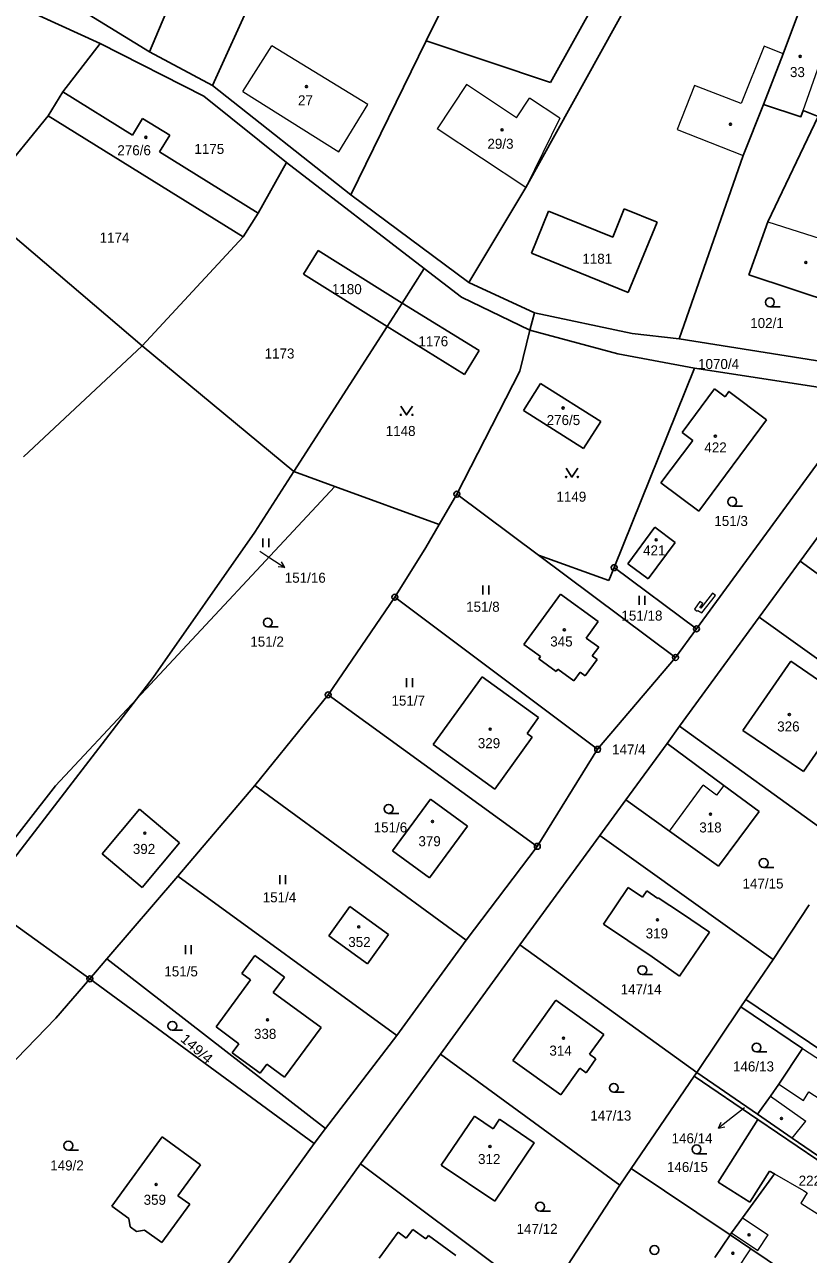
# Model space of a CAD drawing. Extents: x -694609 to -690140, y -1033292 to -1029794.
# Drawn here: x -692957.6 to -692824.6, y -1031527.4 to -1031318.8 of the extents above; entities that cross this region are included whole.
import ezdxf
from ezdxf.enums import TextEntityAlignment as Align

# ---------------------------------------------------------------- set-up
doc = ezdxf.new("R2010")
doc.units = 0
doc.header["$LTSCALE"] = 0.68
for name, color, linetype, lineweight in [('1', 7, 'Continuous', 25), ('13', 7, 'Continuous', 13), ('3', 7, 'Continuous', 25), ('4', 7, 'Continuous', 13), ('5', 7, 'Continuous', 25), ('7', 7, 'Continuous', 13), ('8', 7, 'Continuous', 25)]:
    doc.layers.add(name, color=color, linetype=linetype, lineweight=lineweight)
doc.layers.add('2', color=7, linetype='Continuous')

msp = doc.modelspace()

# ---------------------------------------------------------------- linework, layer by layer
at = {"layer": '1'}
for p, q in [((-692868.43, -1031328.64), (-692843.96, -1031284.77)), ((-692908.54, -1031291.14), (-692925.77, -1031329.14)), ((-692944.79, -1031321.99), (-692982.62, -1031304.77)), ((-692889.51, -1031321.56), (-692884.99, -1031312.35)), ((-692951.8, -1031313.97), (-692936.46, -1031323.39)), ((-692932.61, -1031314.23), (-692936.46, -1031323.39)), ((-692872.57, -1031346.43), (-692854.25, -1031313.29)), ((-692825.19, -1031313.81), (-692828.91, -1031323.74)), ((-692944.79, -1031321.99), (-692951.15, -1031330.19)), ((-692927.23, -1031330.94), (-692944.79, -1031321.99)), ((-692902.3, -1031347.66), (-692889.51, -1031321.56)), ((-692889.51, -1031321.56), (-692868.43, -1031328.64)), ((-692936.46, -1031323.39), (-692925.77, -1031329.14)), ((-692832.29, -1031332.37), (-692828.91, -1031323.74)), ((-692902.3, -1031347.66), (-692925.77, -1031329.14)), ((-692951.15, -1031330.19), (-692953.66, -1031334.24)), ((-692951.15, -1031330.19), (-692939.35, -1031337.52)), ((-692913.22, -1031342.18), (-692927.23, -1031330.94)), ((-692835.69, -1031340.98), (-692832.29, -1031332.37)), ((-692965.91, -1031349.24), (-692953.66, -1031334.24)), ((-692920.53, -1031354.81), (-692953.66, -1031334.24)), ((-692939.35, -1031337.52), (-692937.61, -1031334.72)), ((-692937.61, -1031334.72), (-692933.02, -1031337.57)), ((-692831.53, -1031352.24), (-692822.98, -1031334.36)), ((-692825.53, -1031333.39), (-692822.98, -1031334.36)), ((-692933.02, -1031337.57), (-692934.76, -1031340.37)), ((-692846.59, -1031372.09), (-692835.69, -1031340.98)), ((-692889.84, -1031360.18), (-692913.22, -1031342.18)), ((-692882.25, -1031362.52), (-692902.3, -1031347.66)), ((-692882.25, -1031362.52), (-692872.57, -1031346.43)), ((-692937.71, -1031373.28), (-692965.91, -1031349.24)), ((-692918.02, -1031350.77), (-692920.53, -1031354.81)), ((-692868.72, -1031350.42), (-692871.63, -1031357.56)), ((-692855.89, -1031350.04), (-692850.33, -1031352.3)), ((-692850.33, -1031352.3), (-692855.2, -1031364.25)), ((-692831.53, -1031352.24), (-692834.78, -1031361.26)), ((-692937.71, -1031373.28), (-692920.53, -1031354.81)), ((-692907.81, -1031357.12), (-692910.34, -1031361.15)), ((-692893.56, -1031366.02), (-692907.81, -1031357.12)), ((-692855.2, -1031364.25), (-692871.63, -1031357.56)), ((-692889.84, -1031360.18), (-692893.56, -1031366.02)), ((-692883.53, -1031365.05), (-692889.84, -1031360.18)), ((-692896.14, -1031369.98), (-692910.34, -1031361.15)), ((-692871.14, -1031367.68), (-692882.25, -1031362.52)), ((-692834.78, -1031361.26), (-692818.41, -1031366.65)), ((-692896.14, -1031369.98), (-692893.56, -1031366.02)), ((-692880.52, -1031374.09), (-692893.56, -1031366.02)), ((-692871.89, -1031370.64), (-692883.53, -1031365.05)), ((-692871.89, -1031370.64), (-692871.14, -1031367.68)), ((-692854.56, -1031371.21), (-692871.14, -1031367.68)), ((-692911.95, -1031394.59), (-692896.14, -1031369.98)), ((-692883.02, -1031378.13), (-692896.14, -1031369.98)), ((-692873.63, -1031377.56), (-692871.89, -1031370.64)), ((-692856.97, -1031374.63), (-692871.89, -1031370.64)), ((-692846.59, -1031372.09), (-692854.56, -1031371.21)), ((-692817.73, -1031376.68), (-692846.59, -1031372.09)), ((-692937.71, -1031373.28), (-692957.84, -1031392.12)), ((-692937.71, -1031373.28), (-692911.95, -1031394.59)), ((-692880.52, -1031374.09), (-692883.02, -1031378.13)), ((-692843.95, -1031377.07), (-692856.97, -1031374.63)), ((-692857.6, -1031410.91), (-692843.95, -1031377.07)), ((-692821.53, -1031380.52), (-692843.95, -1031377.07)), ((-692873.63, -1031377.56), (-692884.28, -1031398.46)), ((-692873.01, -1031384.27), (-692870.09, -1031379.65)), ((-692859.88, -1031386.1), (-692870.09, -1031379.65)), ((-692846.05, -1031388), (-692840.56, -1031380.59)), ((-692840.56, -1031380.59), (-692838.76, -1031381.91)), ((-692814.81, -1031381.84), (-692843.63, -1031421.29)), ((-692862.8, -1031390.72), (-692873.01, -1031384.27)), ((-692862.8, -1031390.72), (-692859.88, -1031386.1)), ((-692831.73, -1031385.83), (-692843.23, -1031401.31)), ((-692849.67, -1031396.54), (-692844.26, -1031389.35)), ((-692844.26, -1031389.35), (-692846.05, -1031388)), ((-692918.57, -1031404.9), (-692911.95, -1031394.59)), ((-692911.95, -1031394.59), (-692904.99, -1031397.12)), ((-692938.66, -1031433.21), (-692904.99, -1031397.12)), ((-692904.99, -1031397.12), (-692887.27, -1031403.57)), ((-692843.23, -1031401.31), (-692849.67, -1031396.54)), ((-692884.28, -1031398.46), (-692887.27, -1031403.57)), ((-692870.43, -1031408.8), (-692884.28, -1031398.46)), ((-692826.04, -1031409.79), (-692818.56, -1031399.55)), ((-692887.27, -1031403.57), (-692889.58, -1031407.51)), ((-692855.26, -1031410.24), (-692850.7, -1031404.06)), ((-692850.7, -1031404.06), (-692847.25, -1031406.62)), ((-692935.84, -1031429.54), (-692918.57, -1031404.9)), ((-692847.25, -1031406.62), (-692851.84, -1031412.8)), ((-692847.19, -1031426.16), (-692870.43, -1031408.8)), ((-692858.48, -1031413.08), (-692870.43, -1031408.8)), ((-692851.84, -1031412.8), (-692855.26, -1031410.24)), ((-692832.99, -1031419.3), (-692826.04, -1031409.79)), ((-692820.03, -1031414.16), (-692826.04, -1031409.79)), ((-692858.48, -1031413.08), (-692857.6, -1031410.91)), ((-692857.6, -1031410.91), (-692843.63, -1031421.29)), ((-692860.41, -1031441.73), (-692894.83, -1031415.93)), ((-692872.92, -1031423.92), (-692866.7, -1031415.4)), ((-692860.33, -1031420.05), (-692866.7, -1031415.4)), ((-692862.36, -1031422.86), (-692860.33, -1031420.05)), ((-692846.51, -1031437.82), (-692832.99, -1031419.3)), ((-692832.99, -1031419.3), (-692805.34, -1031439.18)), ((-692860.23, -1031424.41), (-692862.36, -1031422.86)), ((-692847.19, -1031426.16), (-692843.63, -1031421.29)), ((-692870.09, -1031425.98), (-692872.92, -1031423.92)), ((-692861.32, -1031425.89), (-692860.23, -1031424.41)), ((-692870.39, -1031426.39), (-692870.09, -1031425.98)), ((-692867.45, -1031428.54), (-692870.39, -1031426.39)), ((-692862.55, -1031429.24), (-692860.5, -1031426.51)), ((-692860.5, -1031426.51), (-692861.32, -1031425.89)), ((-692860.41, -1031441.73), (-692847.19, -1031426.16)), ((-692835.77, -1031438.56), (-692827.61, -1031426.76)), ((-692821.85, -1031430.74), (-692827.61, -1031426.76)), ((-692867.15, -1031428.13), (-692867.45, -1031428.54)), ((-692864.46, -1031430.1), (-692867.15, -1031428.13)), ((-692864.46, -1031430.1), (-692863.37, -1031428.62)), ((-692863.37, -1031428.62), (-692862.55, -1031429.24)), ((-692938.66, -1031433.21), (-692935.84, -1031429.54)), ((-692880.01, -1031429.43), (-692888.31, -1031440.92)), ((-692870.43, -1031436.35), (-692880.01, -1031429.43)), ((-692991.15, -1031501.5), (-692938.66, -1031433.21)), ((-692952.37, -1031447.9), (-692938.66, -1031433.21)), ((-692906.13, -1031432.49), (-692918.57, -1031447.88)), ((-692870.64, -1031458.19), (-692906.13, -1031432.49)), ((-692872.38, -1031439.04), (-692870.43, -1031436.35)), ((-692825.49, -1031445.49), (-692819.54, -1031436.89)), ((-692877.87, -1031448.48), (-692871.49, -1031439.68)), ((-692871.49, -1031439.68), (-692872.38, -1031439.04)), ((-692848.63, -1031440.72), (-692846.51, -1031437.82)), ((-692846.51, -1031437.82), (-692818.08, -1031458.33)), ((-692835.77, -1031438.56), (-692825.49, -1031445.49)), ((-692888.31, -1031440.92), (-692877.87, -1031448.48)), ((-692870.64, -1031458.19), (-692860.41, -1031441.73)), ((-692855.64, -1031450.32), (-692848.63, -1031440.72)), ((-692839.01, -1031447.84), (-692848.63, -1031440.72)), ((-692991.91, -1031498.52), (-692952.37, -1031447.9)), ((-692931.62, -1031463.24), (-692918.57, -1031447.88)), ((-692882.71, -1031474.09), (-692918.57, -1031447.88)), ((-692833.02, -1031452.27), (-692839.01, -1031447.84)), ((-692944.45, -1031459.46), (-692938.12, -1031451.86)), ((-692938.12, -1031451.86), (-692931.34, -1031457.61)), ((-692895.2, -1031458.95), (-692888.76, -1031450.21)), ((-692888.76, -1031450.21), (-692882.49, -1031454.77)), ((-692860.04, -1031456.36), (-692855.64, -1031450.32)), ((-692848.24, -1031455.6), (-692855.64, -1031450.32)), ((-692839.89, -1031461.55), (-692833.02, -1031452.27)), ((-692882.49, -1031454.77), (-692888.92, -1031463.51)), ((-692873.62, -1031474.9), (-692860.04, -1031456.36)), ((-692860.04, -1031456.36), (-692830.61, -1031477.39)), ((-692839.89, -1031461.55), (-692848.24, -1031455.6)), ((-692931.34, -1031457.61), (-692937.68, -1031465.16)), ((-692882.71, -1031474.09), (-692870.64, -1031458.19)), ((-692937.68, -1031465.16), (-692944.45, -1031459.46)), ((-692888.92, -1031463.51), (-692895.2, -1031458.95)), ((-692931.62, -1031463.24), (-692894.48, -1031490.26)), ((-692859.42, -1031471.41), (-692855.24, -1031465.16)), ((-692852.79, -1031466.8), (-692855.24, -1031465.16)), ((-692852.08, -1031465.74), (-692852.79, -1031466.8)), ((-692850.19, -1031467.01), (-692852.08, -1031465.74)), ((-692906.03, -1031473.36), (-692902.46, -1031468.39)), ((-692902.46, -1031468.39), (-692895.9, -1031473.14)), ((-692850.12, -1031466.9), (-692850.19, -1031467.01)), ((-692846.17, -1031469.53), (-692850.12, -1031466.9)), ((-692824.52, -1031468.13), (-692830.61, -1031477.39)), ((-692961.77, -1031469.68), (-692946.55, -1031480.67)), ((-692841.45, -1031472.73), (-692846.17, -1031469.53)), ((-692859.42, -1031471.41), (-692851.16, -1031476.94)), ((-692846.52, -1031480.19), (-692841.45, -1031472.73)), ((-692899.43, -1031478.1), (-692906.03, -1031473.36)), ((-692895.9, -1031473.14), (-692899.43, -1031478.1)), ((-692882.71, -1031474.09), (-692894.48, -1031490.26)), ((-692887.08, -1031493.44), (-692873.62, -1031474.9)), ((-692873.62, -1031474.9), (-692843.59, -1031496.58)), ((-692943.66, -1031477.27), (-692906.56, -1031506.06)), ((-692920.79, -1031479.75), (-692918.55, -1031476.7)), ((-692918.55, -1031476.7), (-692913.56, -1031480.38)), ((-692851.16, -1031476.94), (-692846.52, -1031480.19)), ((-692830.61, -1031477.39), (-692835.25, -1031484.19)), ((-692946.55, -1031480.67), (-692952.35, -1031487.36)), ((-692946.55, -1031480.67), (-692908.5, -1031508.61)), ((-692925.15, -1031488.83), (-692919.29, -1031480.86)), ((-692919.29, -1031480.86), (-692920.79, -1031479.75)), ((-692913.56, -1031480.38), (-692915.46, -1031482.96)), ((-692915.46, -1031482.96), (-692907.32, -1031488.94)), ((-692874.82, -1031494.5), (-692867.52, -1031484.27)), ((-692859.38, -1031490.13), (-692867.52, -1031484.27)), ((-692836.09, -1031485.44), (-692843.59, -1031496.58)), ((-692835.25, -1031484.19), (-692836.09, -1031485.44)), ((-692825.66, -1031492.47), (-692836.09, -1031485.44)), ((-692820.1, -1031494.39), (-692835.25, -1031484.19)), ((-692952.35, -1031487.36), (-692966.24, -1031501.7)), ((-692921.26, -1031491.69), (-692925.15, -1031488.83)), ((-692913.52, -1031497.37), (-692907.32, -1031488.94)), ((-692922.39, -1031493.23), (-692921.26, -1031491.69)), ((-692894.48, -1031490.26), (-692906.56, -1031506.06)), ((-692861.76, -1031493.47), (-692859.38, -1031490.13)), ((-692917.67, -1031496.69), (-692922.39, -1031493.23)), ((-692887.08, -1031493.44), (-692900.63, -1031512.05)), ((-692856.64, -1031515.64), (-692887.08, -1031493.44)), ((-692860.7, -1031494.23), (-692861.76, -1031493.47)), ((-692825.66, -1031492.47), (-692829.67, -1031498.53)), ((-692916.55, -1031495.16), (-692917.67, -1031496.69)), ((-692913.52, -1031497.37), (-692916.55, -1031495.16)), ((-692874.82, -1031494.5), (-692866.63, -1031500.32)), ((-692866.63, -1031500.32), (-692863.44, -1031495.84)), ((-692863.44, -1031495.84), (-692862.38, -1031496.59)), ((-692862.38, -1031496.59), (-692860.7, -1031494.23)), ((-692844.02, -1031497.2), (-692854.72, -1031512.83)), ((-692843.59, -1031496.58), (-692844.02, -1031497.2)), ((-692833.22, -1031504.54), (-692844.02, -1031497.2)), ((-692843.59, -1031496.58), (-692833.3, -1031503.64)), ((-692829.67, -1031498.53), (-692831.1, -1031500.54)), ((-692831.1, -1031500.54), (-692833.3, -1031503.64)), ((-692886.95, -1031512.28), (-692881.3, -1031503.98)), ((-692878.14, -1031506.13), (-692881.3, -1031503.98)), ((-692833.3, -1031503.64), (-692827.38, -1031507.7)), ((-692906.56, -1031506.06), (-692908.5, -1031508.61)), ((-692877.03, -1031504.49), (-692878.14, -1031506.13)), ((-692833.22, -1031504.54), (-692839.98, -1031515.18)), ((-692814.52, -1031517.26), (-692833.22, -1031504.54)), ((-692942.84, -1031519.24), (-692934.32, -1031507.47)), ((-692934.32, -1031507.47), (-692927.78, -1031512.22)), ((-692813.29, -1031517.36), (-692827.38, -1031507.7)), ((-692908.5, -1031508.61), (-692938.37, -1031550.06)), ((-692927.78, -1031512.22), (-692931.62, -1031517.46)), ((-692914.01, -1031530.6), (-692900.63, -1031512.05)), ((-692900.63, -1031512.05), (-692869.49, -1031535.38)), ((-692886.95, -1031512.28), (-692877.87, -1031518.37)), ((-692854.72, -1031512.83), (-692856.64, -1031515.64)), ((-692837.93, -1031524.09), (-692854.72, -1031512.83)), ((-692830.39, -1031513.76), (-692835.84, -1031521.22)), ((-692834.61, -1031518.55), (-692831.24, -1031513.27)), ((-692831.24, -1031513.27), (-692830.39, -1031513.76)), ((-692865.52, -1031529.27), (-692856.64, -1031515.64)), ((-692839.98, -1031515.18), (-692834.61, -1031518.55)), ((-692929.6, -1031518.91), (-692934.37, -1031525.39)), ((-692931.62, -1031517.46), (-692929.6, -1031518.91)), ((-692939.94, -1031521.34), (-692942.84, -1031519.24)), ((-692939.73, -1031522.71), (-692939.94, -1031521.34)), ((-692938.66, -1031523.51), (-692939.73, -1031522.71)), ((-692891.77, -1031523.16), (-692892.88, -1031524.66)), ((-692889.55, -1031524.79), (-692891.77, -1031523.16)), ((-692837.69, -1031523.76), (-692835.84, -1031521.22)), ((-692937.3, -1031523.28), (-692938.66, -1031523.51)), ((-692934.37, -1031525.39), (-692937.3, -1031523.28)), ((-692897.5, -1031528.03), (-692894.26, -1031523.64)), ((-692892.88, -1031524.66), (-692894.26, -1031523.64)), ((-692889.11, -1031524.19), (-692889.55, -1031524.79)), ((-692884.48, -1031527.6), (-692889.11, -1031524.19)), ((-692840.5, -1031527.92), (-692837.93, -1031524.09)), ((-692837.93, -1031524.09), (-692837.69, -1031523.76)), ((-692834.4, -1031526.46), (-692837.93, -1031524.09)), ((-692824.77, -1031532.91), (-692834.4, -1031526.46))]:
    msp.add_line(p, q, dxfattribs=at)
for points in [[(-692832.29, -1031332.37), (-692825.93, -1031334.43), (-692825.53, -1031333.39)], [(-692934.76, -1031340.37), (-692918.02, -1031350.77), (-692913.22, -1031342.18)], [(-692868.72, -1031350.42), (-692857.84, -1031354.84), (-692855.89, -1031350.04)], [(-692838.76, -1031381.91), (-692838.12, -1031381.02), (-692831.73, -1031385.83)], [(-692889.58, -1031407.51), (-692894.83, -1031415.93), (-692906.13, -1031432.49)], [(-692946.55, -1031480.67), (-692943.66, -1031477.27), (-692931.62, -1031463.24)], [(-692877.87, -1031518.37), (-692871.15, -1031508.49), (-692877.03, -1031504.49)]]:
    msp.add_lwpolyline(points, dxfattribs=at)
at = {"layer": '13'}
msp.add_lwpolyline([(-692842.88, -1031417.78), (-692843.06, -1031417.68), (-692842.57, -1031417.01), (-692843.05, -1031416.67), (-692843.95, -1031417.95), (-692843.5, -1031418.28), (-692843.42, -1031418.17), (-692842.72, -1031418.56), (-692840.43, -1031415.61), (-692840.9, -1031415.24)], close=True, dxfattribs=at)
at = {"layer": '3'}
for p, q in [((-692831.183, -1031366.65), (-692829.433, -1031366.65)), ((-692837.573, -1031400.48), (-692835.823, -1031400.48)), ((-692917.221, -1031407.44), (-692917.221, -1031405.94)), ((-692916.22, -1031407.44), (-692916.22, -1031405.94)), ((-692879.871, -1031415.45), (-692879.871, -1031413.95)), ((-692878.87, -1031415.45), (-692878.87, -1031413.95)), ((-692853.381, -1031417.21), (-692853.381, -1031415.71)), ((-692852.38, -1031417.21), (-692852.38, -1031415.71)), ((-692916.373, -1031420.97), (-692914.623, -1031420.97)), ((-692892.821, -1031431.17), (-692892.821, -1031429.67)), ((-692891.82, -1031431.17), (-692891.82, -1031429.67)), ((-692895.863, -1031452.59), (-692894.113, -1031452.59)), ((-692832.243, -1031461.76), (-692830.493, -1031461.76)), ((-692914.341, -1031464.58), (-692914.341, -1031463.08)), ((-692913.34, -1031464.58), (-692913.34, -1031463.08)), ((-692930.361, -1031476.47), (-692930.361, -1031474.97)), ((-692929.36, -1031476.47), (-692929.36, -1031474.97)), ((-692852.823, -1031479.93), (-692851.073, -1031479.93)), ((-692932.573, -1031489.38), (-692930.823, -1031489.38)), ((-692833.443, -1031493.07), (-692831.693, -1031493.07)), ((-692857.663, -1031499.9), (-692855.913, -1031499.9)), ((-692950.213, -1031509.71), (-692948.463, -1031509.71)), ((-692843.623, -1031510.33), (-692841.873, -1031510.33)), ((-692870.173, -1031520.07), (-692868.423, -1031520.07))]:
    msp.add_line(p, q, dxfattribs=at)
for points in [[(-692893.81, -1031383.499), (-692892.81, -1031385), (-692891.81, -1031383.499)], [(-692865.76, -1031394.039), (-692864.76, -1031395.54), (-692863.76, -1031394.039)]]:
    msp.add_lwpolyline(points, dxfattribs=at)
for centre, radius in [((-692831.1829, -1031365.8998), 0.75), ((-692893.81, -1031384.9995), 0.1), ((-692891.81, -1031384.9995), 0.1), ((-692865.76, -1031395.5395), 0.1), ((-692863.76, -1031395.5395), 0.1), ((-692837.5729, -1031399.7298), 0.75), ((-692916.3729, -1031420.2198), 0.75), ((-692895.8629, -1031451.8398), 0.75), ((-692832.2429, -1031461.0098), 0.75), ((-692852.8229, -1031479.1798), 0.75), ((-692932.5729, -1031488.6298), 0.75), ((-692833.4429, -1031492.3198), 0.75), ((-692857.6629, -1031499.1498), 0.75), ((-692950.2129, -1031508.9598), 0.75), ((-692843.6229, -1031509.5798), 0.75), ((-692870.1729, -1031519.3198), 0.75), ((-692850.7729, -1031526.6598), 0.75)]:
    msp.add_circle(centre, radius, dxfattribs=at)
at = {"layer": '4'}
for p, q in [((-692825.53, -1031333.39), (-692819.34, -1031315.7)), ((-692920.63, -1031330.16), (-692915.69, -1031322.37)), ((-692899.37, -1031332.35), (-692915.69, -1031322.37)), ((-692832.16, -1031322.45), (-692836.03, -1031332.2)), ((-692828.91, -1031323.74), (-692832.16, -1031322.45)), ((-692882.68, -1031328.98), (-692887.64, -1031336.49)), ((-692874.18, -1031334.58), (-692882.68, -1031328.98)), ((-692843.98, -1031329.12), (-692846.91, -1031336.56)), ((-692836.03, -1031332.2), (-692843.98, -1031329.12)), ((-692920.63, -1031330.16), (-692904.29, -1031340.4)), ((-692904.29, -1031340.4), (-692899.37, -1031332.35)), ((-692874.18, -1031334.58), (-692871.99, -1031331.26)), ((-692866.82, -1031334.67), (-692871.99, -1031331.26)), ((-692846.91, -1031336.56), (-692835.69, -1031340.98)), ((-692831.53, -1031352.24), (-692815.33, -1031357.4)), ((-692848.24, -1031455.6), (-692842.48, -1031447.82)), ((-692840.23, -1031449.49), (-692842.48, -1031447.82)), ((-692839.01, -1031447.84), (-692840.23, -1031449.49)), ((-692825.66, -1031492.47), (-692806.62, -1031504.84)), ((-692831.1, -1031500.54), (-692825.11, -1031504.79)), ((-692827.38, -1031507.7), (-692825.11, -1031504.79)), ((-692830.39, -1031513.76), (-692825.46, -1031516.59)), ((-692825.46, -1031516.59), (-692824.88, -1031516.97)), ((-692824.88, -1031516.97), (-692825.95, -1031518.71)), ((-692825.95, -1031518.71), (-692822.35, -1031520.99)), ((-692835.84, -1031521.22), (-692831.47, -1031524.08)), ((-692837.69, -1031523.76), (-692833.25, -1031526.75)), ((-692833.25, -1031526.75), (-692831.47, -1031524.08)), ((-692836.94, -1031530.31), (-692834.4, -1031526.46))]:
    msp.add_line(p, q, dxfattribs=at)
for points in [[(-692866.82, -1031334.67), (-692872.57, -1031346.43), (-692887.64, -1031336.49)], [(-692829.67, -1031498.53), (-692825.5, -1031501.29), (-692824.56, -1031499.84), (-692809.66, -1031509.52)]]:
    msp.add_lwpolyline(points, dxfattribs=at)
at = {"layer": '5'}
for centre in [(-692826.0368, -1031324.1792), (-692909.8168, -1031329.3092), (-692876.6268, -1031336.6392), (-692837.8768, -1031335.6992), (-692937.0468, -1031337.9192), (-692825.0868, -1031359.1392), (-692866.2768, -1031383.8292), (-692840.4368, -1031388.6092), (-692850.4668, -1031406.2092), (-692866.0568, -1031421.4592), (-692827.8768, -1031435.8392), (-692878.6268, -1031438.2992), (-692888.4268, -1031453.9692), (-692841.2668, -1031452.7192), (-692937.2468, -1031455.9692), (-692850.2668, -1031470.6592), (-692900.9468, -1031471.8592), (-692916.4068, -1031487.6192), (-692866.2068, -1031490.7292), (-692829.2268, -1031504.3392), (-692878.6668, -1031509.0992), (-692935.3268, -1031515.5392), (-692834.7168, -1031524.0992), (-692837.4568, -1031527.2192)]:
    msp.add_circle(centre, 0.175, dxfattribs=at)
at = {"layer": '7'}
for p, q in [((-692913.483, -1031410.904), (-692914.05, -1031409.939)), ((-692839.915, -1031505.998), (-692838.817, -1031505.776))]:
    msp.add_line(p, q, dxfattribs=at)
for points in [[(-692917.74, -1031408.14), (-692916, -1031409.27), (-692913.483, -1031410.904), (-692914.596, -1031410.779)], [(-692835.51, -1031502.56), (-692837.55, -1031504.15), (-692839.915, -1031505.998), (-692839.434, -1031504.986)]]:
    msp.add_lwpolyline(points, dxfattribs=at)
at = {"layer": '8'}
for centre, radius in [((-692884.28, -1031398.4599), 0.5), ((-692884.28, -1031398.4599), 0.0303), ((-692857.6, -1031410.9099), 0.5), ((-692857.6, -1031410.9099), 0.0303), ((-692894.83, -1031415.9299), 0.5), ((-692894.83, -1031415.9299), 0.0303), ((-692843.63, -1031421.2899), 0.5), ((-692843.63, -1031421.2899), 0.0303), ((-692847.19, -1031426.1599), 0.5), ((-692847.19, -1031426.1599), 0.0303), ((-692906.13, -1031432.4899), 0.5), ((-692906.13, -1031432.4899), 0.0303), ((-692860.41, -1031441.7299), 0.5), ((-692860.41, -1031441.7299), 0.0303), ((-692870.64, -1031458.1899), 0.5), ((-692870.64, -1031458.1899), 0.0303), ((-692946.55, -1031480.6699), 0.5), ((-692946.55, -1031480.6699), 0.0303)]:
    msp.add_circle(centre, radius, dxfattribs=at)

# ---------------------------------------------------------------- texts
at = {"layer": '2'}
for s, p in [('33', (-692826.509, -1031327.695)), ('27', (-692909.979, -1031332.485)), ('276/6', (-692939.05, -1031340.955)), ('1175', (-692926.29, -1031340.725)), ('29/3', (-692876.889, -1031339.855)), ('1174', (-692942.37, -1031355.775)), ('1181', (-692860.47, -1031359.355)), ('1180', (-692902.96, -1031364.515)), ('102/1', (-692831.67, -1031370.265)), ('1176', (-692888.29, -1031373.355)), ('1173', (-692914.38, -1031375.435)), ('1070/4', (-692839.89, -1031377.215)), ('276/5', (-692866.21, -1031386.725)), ('1148', (-692893.83, -1031388.575)), ('422', (-692840.399, -1031391.372)), ('1149', (-692864.87, -1031399.725)), ('151/3', (-692837.76, -1031403.845)), ('421', (-692850.799, -1031408.832)), ('151/8', (-692879.87, -1031418.395)), ('151/18', (-692852.89, -1031419.892)), ('151/2', (-692916.49, -1031424.305)), ('345', (-692866.549, -1031424.285)), ('151/7', (-692892.54, -1031434.315)), ('326', (-692828.039, -1031438.705)), ('329', (-692878.839, -1031441.535)), ('147/4', (-692855.11, -1031442.605)), ('151/6', (-692895.56, -1031455.825)), ('318', (-692841.259, -1031455.835)), ('392', (-692937.369, -1031459.475)), ('379', (-692888.919, -1031458.165)), ('147/15', (-692832.35, -1031465.345)), ('151/4', (-692914.39, -1031467.685)), ('319', (-692850.359, -1031473.805)), ('352', (-692900.819, -1031475.265)), ('151/5', (-692931.08, -1031480.255)), ('147/14', (-692853.03, -1031483.285)), ('338', (-692916.819, -1031490.845)), ('314', (-692866.699, -1031493.685)), ('146/13', (-692833.96, -1031496.375)), ('147/13', (-692858.17, -1031504.705)), ('312', (-692878.799, -1031512.085)), ('149/2', (-692950.44, -1031513.165)), ('146/15', (-692845.17, -1031513.435)), ('222', (-692824.399, -1031515.745)), ('359', (-692935.539, -1031518.995)), ('147/12', (-692870.68, -1031523.925))]:
    msp.add_text(s, height=1.7, dxfattribs=at).set_placement(p, align=Align.CENTER)
msp.add_text('151/16', height=1.7, dxfattribs=at).set_placement((-692913.49, -1031413.475))
at = {"layer": '2', "width": 1.1}
msp.add_text('149/4', height=1.7, rotation=319, dxfattribs=at).set_placement((-692928.9746, -1031493.1375), align=Align.CENTER)
at = {"layer": '2'}
msp.add_text('146/14', height=1.7, dxfattribs=at).set_placement((-692840.909, -1031508.565), align=Align.RIGHT)

doc.saveas('drawing.dxf')
